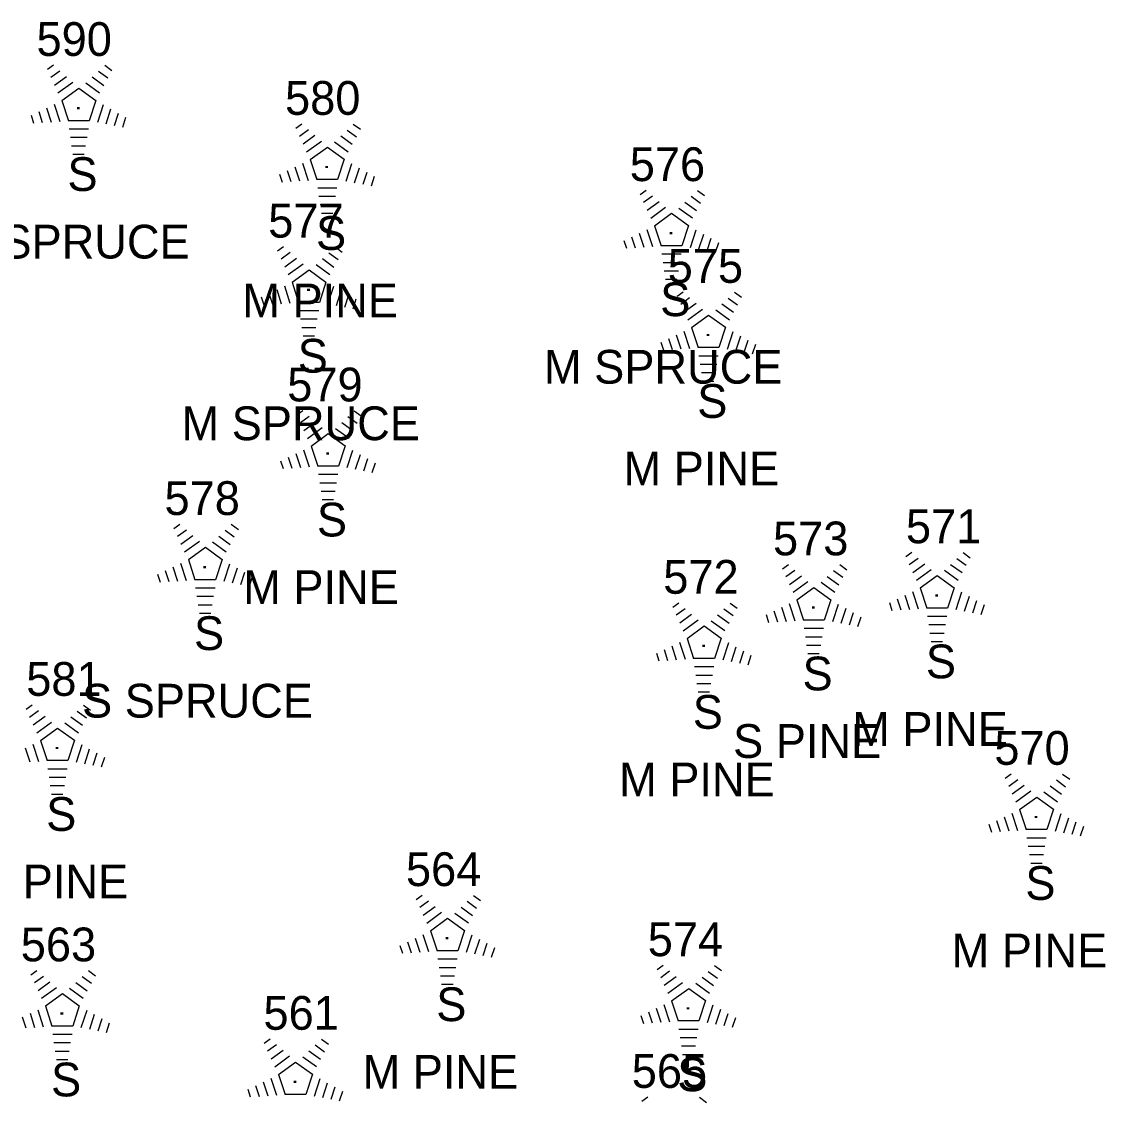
# Model space of a CAD drawing. Extents: x 1545627 to 1546562, y 571176 to 576667.
# Drawn here: x 1546217.9 to 1546282, y 571977 to 572041 of the extents above; entities that cross this region are included whole.
import ezdxf

# ---------------------------------------------------------------- set-up
doc = ezdxf.new("R2010")
doc.units = 0
for name, color, linetype in [('L_A', 7, 'Continuous'), ('L_C', 7, 'Continuous'), ('L_I', 7, 'Continuous'), ('LTC', 7, 'Continuous')]:
    doc.layers.add(name, color=color, linetype=linetype)

msp = doc.modelspace()

# ---------------------------------------------------------------- linework, layer by layer
at = {"layer": 'LTC'}
for p, q in [((1546219.373, 572038.219), (1546219.728, 572038.477)), ((1546222.772, 572038.46), (1546223.191, 572038.155)), ((1546219.583, 572037.754), (1546220.112, 572038.138)), ((1546219.793, 572037.288), (1546220.496, 572037.799)), ((1546222.03, 572037.763), (1546222.709, 572037.269)), ((1546222.4, 572038.111), (1546222.95, 572037.712)), ((1546220.002, 572036.822), (1546220.88, 572037.46)), ((1546221.658, 572037.415), (1546222.468, 572036.826)), ((1546220.227, 572036.367), (1546221.238, 572037.102)), ((1546221.238, 572037.102), (1546222.235, 572036.377)), ((1546219.317, 572035.932), (1546219.588, 572035.096)), ((1546219.772, 572036.148), (1546220.103, 572035.129)), ((1546220.227, 572036.367), (1546220.614, 572035.174)), ((1546222.235, 572036.377), (1546221.844, 572035.174)), ((1546222.673, 572036.106), (1546222.335, 572035.066)), ((1546223.118, 572035.855), (1546222.83, 572034.971)), ((1546218.406, 572035.498), (1546218.558, 572035.03)), ((1546218.861, 572035.715), (1546219.073, 572035.063)), ((1546223.562, 572035.605), (1546223.325, 572034.876)), ((1546224.006, 572035.355), (1546223.82, 572034.781)), ((1546221.844, 572035.174), (1546220.614, 572035.174)), ((1546221.806, 572034.674), (1546220.661, 572034.674)), ((1546234.089, 572034.729), (1546234.443, 572034.986)), ((1546234.299, 572034.264), (1546234.828, 572034.648)), ((1546237.116, 572034.621), (1546237.666, 572034.222)), ((1546237.487, 572034.969), (1546237.906, 572034.665)), ((1546221.722, 572034.174), (1546220.734, 572034.174)), ((1546234.508, 572033.798), (1546235.212, 572034.309)), ((1546234.718, 572033.332), (1546235.596, 572033.97)), ((1546236.374, 572033.924), (1546237.183, 572033.336)), ((1546236.745, 572034.273), (1546237.424, 572033.779)), ((1546221.638, 572033.674), (1546220.807, 572033.674)), ((1546234.942, 572032.877), (1546235.954, 572033.611)), ((1546235.954, 572033.611), (1546236.951, 572032.886)), ((1546221.555, 572033.174), (1546220.88, 572033.174)), ((1546234.488, 572032.658), (1546234.818, 572031.639)), ((1546234.942, 572032.877), (1546235.329, 572031.684)), ((1546236.951, 572032.886), (1546236.56, 572031.684)), ((1546237.388, 572032.616), (1546237.051, 572031.576)), ((1546233.121, 572032.008), (1546233.274, 572031.54)), ((1546233.577, 572032.225), (1546233.789, 572031.573)), ((1546234.032, 572032.442), (1546234.304, 572031.606)), ((1546237.833, 572032.365), (1546237.546, 572031.481)), ((1546238.278, 572032.115), (1546238.041, 572031.386)), ((1546236.56, 572031.684), (1546235.329, 572031.684)), ((1546238.722, 572031.865), (1546238.535, 572031.291)), ((1546236.521, 572031.184), (1546235.377, 572031.184)), ((1546254.468, 572030.805), (1546254.822, 572031.063)), ((1546254.677, 572030.34), (1546255.206, 572030.724)), ((1546257.495, 572030.697), (1546258.044, 572030.298)), ((1546257.866, 572031.045), (1546258.285, 572030.741)), ((1546236.438, 572030.684), (1546235.449, 572030.684)), ((1546236.354, 572030.184), (1546235.522, 572030.184)), ((1546254.887, 572029.874), (1546255.59, 572030.385)), ((1546255.096, 572029.408), (1546255.975, 572030.046)), ((1546257.124, 572030.349), (1546257.803, 572029.855)), ((1546236.27, 572029.684), (1546235.595, 572029.684)), ((1546255.321, 572028.953), (1546256.333, 572029.688)), ((1546256.333, 572029.688), (1546257.33, 572028.963)), ((1546256.753, 572030), (1546257.562, 572029.412)), ((1546255.321, 572028.953), (1546255.708, 572027.76)), ((1546257.33, 572028.963), (1546256.938, 572027.76)), ((1546253.955, 572028.301), (1546254.167, 572027.649)), ((1546254.411, 572028.518), (1546254.682, 572027.682)), ((1546254.866, 572028.734), (1546255.197, 572027.715)), ((1546257.767, 572028.692), (1546257.429, 572027.652)), ((1546258.212, 572028.441), (1546257.924, 572027.557)), ((1546258.656, 572028.191), (1546258.419, 572027.462)), ((1546233.007, 572027.458), (1546233.361, 572027.716)), ((1546236.405, 572027.699), (1546236.824, 572027.394)), ((1546253.5, 572028.084), (1546253.652, 572027.616)), ((1546256.938, 572027.76), (1546255.708, 572027.76)), ((1546259.1, 572027.941), (1546258.914, 572027.367)), ((1546233.216, 572026.993), (1546233.745, 572027.377)), ((1546233.426, 572026.527), (1546234.129, 572027.038)), ((1546235.663, 572027.002), (1546236.342, 572026.508)), ((1546236.034, 572027.351), (1546236.583, 572026.951)), ((1546256.9, 572027.26), (1546255.755, 572027.26)), ((1546233.635, 572026.061), (1546234.514, 572026.699)), ((1546233.86, 572025.606), (1546234.872, 572026.341)), ((1546234.872, 572026.341), (1546235.869, 572025.616)), ((1546235.292, 572026.654), (1546236.101, 572026.065)), ((1546256.816, 572026.76), (1546255.828, 572026.76)), ((1546256.733, 572026.26), (1546255.901, 572026.26)), ((1546233.86, 572025.606), (1546234.247, 572024.413)), ((1546235.869, 572025.616), (1546235.477, 572024.413)), ((1546256.649, 572025.76), (1546255.974, 572025.76)), ((1546232.494, 572024.954), (1546232.706, 572024.303)), ((1546232.95, 572025.171), (1546233.221, 572024.336)), ((1546233.405, 572025.387), (1546233.736, 572024.368)), ((1546236.306, 572025.345), (1546235.968, 572024.306)), ((1546236.751, 572025.095), (1546236.463, 572024.21)), ((1546256.66, 572024.778), (1546257.014, 572025.036)), ((1546260.058, 572025.018), (1546260.477, 572024.714)), ((1546232.039, 572024.738), (1546232.191, 572024.27)), ((1546235.477, 572024.413), (1546234.247, 572024.413)), ((1546237.195, 572024.845), (1546236.958, 572024.115)), ((1546237.639, 572024.594), (1546237.453, 572024.02)), ((1546256.869, 572024.313), (1546257.398, 572024.697)), ((1546257.079, 572023.847), (1546257.782, 572024.358)), ((1546259.316, 572024.322), (1546259.995, 572023.828)), ((1546259.687, 572024.67), (1546260.236, 572024.271)), ((1546235.439, 572023.913), (1546234.294, 572023.913)), ((1546257.288, 572023.381), (1546258.167, 572024.019)), ((1546257.513, 572022.926), (1546258.525, 572023.661)), ((1546258.525, 572023.661), (1546259.522, 572022.936)), ((1546258.945, 572023.973), (1546259.754, 572023.385)), ((1546235.355, 572023.413), (1546234.367, 572023.413)), ((1546235.272, 572022.913), (1546234.44, 572022.913)), ((1546235.188, 572022.413), (1546234.513, 572022.413)), ((1546256.603, 572022.491), (1546256.874, 572021.655)), ((1546257.058, 572022.707), (1546257.389, 572021.688)), ((1546257.513, 572022.926), (1546257.9, 572021.733)), ((1546259.522, 572022.936), (1546259.13, 572021.733)), ((1546259.959, 572022.665), (1546259.621, 572021.625)), ((1546260.404, 572022.414), (1546260.116, 572021.53)), ((1546255.692, 572022.057), (1546255.844, 572021.589)), ((1546256.147, 572022.274), (1546256.359, 572021.622)), ((1546259.13, 572021.733), (1546257.9, 572021.733)), ((1546260.848, 572022.164), (1546260.611, 572021.435)), ((1546261.292, 572021.914), (1546261.106, 572021.34)), ((1546259.092, 572021.233), (1546257.947, 572021.233)), ((1546259.008, 572020.733), (1546258.02, 572020.733)), ((1546258.925, 572020.233), (1546258.093, 572020.233)), ((1546258.841, 572019.733), (1546258.166, 572019.733)), ((1546234.142, 572017.755), (1546234.496, 572018.013)), ((1546237.54, 572017.995), (1546237.959, 572017.691)), ((1546234.351, 572017.29), (1546234.88, 572017.674)), ((1546234.561, 572016.824), (1546235.264, 572017.335)), ((1546236.798, 572017.299), (1546237.477, 572016.805)), ((1546237.169, 572017.647), (1546237.718, 572017.248)), ((1546234.77, 572016.358), (1546235.649, 572016.996)), ((1546234.995, 572015.903), (1546236.007, 572016.638)), ((1546236.007, 572016.638), (1546237.004, 572015.913)), ((1546236.427, 572016.95), (1546237.236, 572016.362)), ((1546234.085, 572015.468), (1546234.356, 572014.632)), ((1546234.54, 572015.684), (1546234.871, 572014.665)), ((1546234.995, 572015.903), (1546235.382, 572014.71)), ((1546237.004, 572015.913), (1546236.612, 572014.71)), ((1546237.441, 572015.642), (1546237.103, 572014.602)), ((1546237.886, 572015.391), (1546237.598, 572014.507)), ((1546233.174, 572015.034), (1546233.326, 572014.566)), ((1546233.629, 572015.251), (1546233.841, 572014.599)), ((1546236.612, 572014.71), (1546235.382, 572014.71)), ((1546238.33, 572015.141), (1546238.093, 572014.412)), ((1546238.774, 572014.891), (1546238.588, 572014.317)), ((1546236.574, 572014.21), (1546235.429, 572014.21)), ((1546236.49, 572013.71), (1546235.502, 572013.71)), ((1546236.407, 572013.21), (1546235.575, 572013.21)), ((1546236.323, 572012.71), (1546235.648, 572012.71)), ((1546226.865, 572011.027), (1546227.22, 572011.284)), ((1546227.075, 572010.561), (1546227.604, 572010.945)), ((1546229.892, 572010.919), (1546230.442, 572010.52)), ((1546230.264, 572011.267), (1546230.683, 572010.962)), ((1546227.284, 572010.095), (1546227.988, 572010.607)), ((1546227.494, 572009.63), (1546228.372, 572010.267)), ((1546229.15, 572010.222), (1546229.96, 572009.633)), ((1546229.522, 572010.57), (1546230.201, 572010.077)), ((1546227.719, 572009.175), (1546228.73, 572009.909)), ((1546228.73, 572009.909), (1546229.727, 572009.184)), ((1546270.196, 572009.352), (1546270.551, 572009.609)), ((1546273.595, 572009.592), (1546274.014, 572009.288)), ((1546227.264, 572008.955), (1546227.595, 572007.936)), ((1546227.719, 572009.175), (1546228.106, 572007.981)), ((1546229.727, 572009.184), (1546229.336, 572007.981)), ((1546230.165, 572008.913), (1546229.827, 572007.874)), ((1546262.895, 572008.637), (1546263.249, 572008.894)), ((1546266.293, 572008.877), (1546266.712, 572008.573)), ((1546270.406, 572008.886), (1546270.935, 572009.27)), ((1546270.616, 572008.42), (1546271.319, 572008.932)), ((1546272.853, 572008.895), (1546273.532, 572008.402)), ((1546273.224, 572009.244), (1546273.773, 572008.845)), ((1546225.898, 572008.306), (1546226.05, 572007.838)), ((1546226.353, 572008.522), (1546226.565, 572007.871)), ((1546226.809, 572008.739), (1546227.08, 572007.904)), ((1546230.609, 572008.663), (1546230.322, 572007.778)), ((1546231.054, 572008.413), (1546230.817, 572007.683)), ((1546263.104, 572008.171), (1546263.633, 572008.556)), ((1546265.922, 572008.529), (1546266.471, 572008.13)), ((1546270.825, 572007.955), (1546271.704, 572008.593)), ((1546271.05, 572007.5), (1546272.061, 572008.234)), ((1546272.061, 572008.234), (1546273.059, 572007.509)), ((1546272.481, 572008.547), (1546273.291, 572007.958)), ((1546229.336, 572007.981), (1546228.106, 572007.981)), ((1546231.498, 572008.162), (1546231.312, 572007.588)), ((1546263.314, 572007.706), (1546264.018, 572008.217)), ((1546263.523, 572007.24), (1546264.402, 572007.878)), ((1546265.18, 572007.832), (1546265.989, 572007.243)), ((1546265.551, 572008.181), (1546266.23, 572007.687)), ((1546229.298, 572007.481), (1546228.153, 572007.481)), ((1546229.214, 572006.981), (1546228.226, 572006.981)), ((1546263.748, 572006.785), (1546264.76, 572007.519)), ((1546264.76, 572007.519), (1546265.757, 572006.794)), ((1546270.14, 572007.064), (1546270.411, 572006.229)), ((1546270.595, 572007.28), (1546270.926, 572006.261)), ((1546271.05, 572007.5), (1546271.437, 572006.306)), ((1546273.059, 572007.509), (1546272.667, 572006.306)), ((1546273.496, 572007.238), (1546273.158, 572006.199)), ((1546273.941, 572006.988), (1546273.653, 572006.103)), ((1546229.13, 572006.481), (1546228.299, 572006.481)), ((1546256.396, 572006.362), (1546256.751, 572006.62)), ((1546259.795, 572006.603), (1546260.214, 572006.298)), ((1546262.838, 572006.349), (1546263.109, 572005.514)), ((1546263.293, 572006.566), (1546263.624, 572005.546)), ((1546263.748, 572006.785), (1546264.135, 572005.591)), ((1546265.757, 572006.794), (1546265.365, 572005.591)), ((1546266.194, 572006.523), (1546265.856, 572005.484)), ((1546269.229, 572006.631), (1546269.381, 572006.163)), ((1546269.684, 572006.848), (1546269.896, 572006.196)), ((1546272.667, 572006.306), (1546271.437, 572006.306)), ((1546274.385, 572006.738), (1546274.148, 572006.008)), ((1546274.829, 572006.488), (1546274.643, 572005.913)), ((1546229.047, 572005.981), (1546228.372, 572005.981)), ((1546256.606, 572005.897), (1546257.135, 572006.281)), ((1546256.816, 572005.431), (1546257.519, 572005.942)), ((1546259.053, 572005.906), (1546259.732, 572005.412)), ((1546259.423, 572006.254), (1546259.973, 572005.855)), ((1546261.927, 572005.916), (1546262.079, 572005.448)), ((1546262.383, 572006.133), (1546262.594, 572005.481)), ((1546266.639, 572006.273), (1546266.351, 572005.388)), ((1546267.083, 572006.023), (1546266.846, 572005.293)), ((1546267.528, 572005.773), (1546267.341, 572005.198)), ((1546272.629, 572005.806), (1546271.484, 572005.806)), ((1546257.025, 572004.965), (1546257.903, 572005.603)), ((1546257.25, 572004.51), (1546258.261, 572005.245)), ((1546258.261, 572005.245), (1546259.258, 572004.52)), ((1546258.681, 572005.558), (1546259.491, 572004.969)), ((1546265.365, 572005.591), (1546264.135, 572005.591)), ((1546265.327, 572005.091), (1546264.183, 572005.091)), ((1546272.545, 572005.306), (1546271.557, 572005.306)), ((1546257.25, 572004.51), (1546257.637, 572003.317)), ((1546259.258, 572004.52), (1546258.867, 572003.317)), ((1546265.243, 572004.591), (1546264.255, 572004.591)), ((1546272.461, 572004.806), (1546271.63, 572004.806)), ((1546255.884, 572003.858), (1546256.096, 572003.206)), ((1546256.34, 572004.075), (1546256.611, 572003.239)), ((1546256.795, 572004.291), (1546257.126, 572003.272)), ((1546259.696, 572004.249), (1546259.358, 572003.209)), ((1546260.14, 572003.998), (1546259.853, 572003.114)), ((1546260.585, 572003.748), (1546260.348, 572003.019)), ((1546265.16, 572004.091), (1546264.328, 572004.091)), ((1546272.378, 572004.306), (1546271.703, 572004.306)), ((1546255.429, 572003.641), (1546255.581, 572003.173)), ((1546258.867, 572003.317), (1546257.637, 572003.317)), ((1546261.029, 572003.498), (1546260.843, 572002.924)), ((1546265.076, 572003.591), (1546264.401, 572003.591)), ((1546258.829, 572002.817), (1546257.684, 572002.817)), ((1546258.745, 572002.317), (1546257.757, 572002.317)), ((1546258.661, 572001.817), (1546257.83, 572001.817)), ((1546258.578, 572001.317), (1546257.903, 572001.317)), ((1546218.113, 572000.314), (1546218.468, 572000.572)), ((1546221.512, 572000.555), (1546221.931, 572000.25)), ((1546218.323, 571999.849), (1546218.852, 572000.233)), ((1546218.532, 571999.383), (1546219.236, 571999.894)), ((1546221.14, 572000.207), (1546221.69, 571999.807)), ((1546218.742, 571998.917), (1546219.62, 571999.555)), ((1546220.398, 571999.51), (1546221.208, 571998.921)), ((1546220.77, 571999.858), (1546221.449, 571999.364)), ((1546218.967, 571998.462), (1546219.978, 571999.197)), ((1546219.978, 571999.197), (1546220.975, 571998.472)), ((1546218.057, 571998.027), (1546218.328, 571997.192)), ((1546218.512, 571998.243), (1546218.843, 571997.224)), ((1546218.967, 571998.462), (1546219.354, 571997.269)), ((1546220.975, 571998.472), (1546220.584, 571997.269)), ((1546221.413, 571998.201), (1546221.075, 571997.162)), ((1546221.857, 571997.951), (1546221.57, 571997.066)), ((1546222.302, 571997.701), (1546222.065, 571996.971)), ((1546222.746, 571997.45), (1546222.56, 571996.876)), ((1546220.584, 571997.269), (1546219.354, 571997.269)), ((1546220.546, 571996.769), (1546219.401, 571996.769)), ((1546220.462, 571996.269), (1546219.474, 571996.269)), ((1546276.085, 571996.229), (1546276.44, 571996.486)), ((1546276.295, 571995.763), (1546276.824, 571996.147)), ((1546279.113, 571996.121), (1546279.662, 571995.721)), ((1546279.484, 571996.469), (1546279.903, 571996.164)), ((1546220.378, 571995.769), (1546219.547, 571995.769)), ((1546276.505, 571995.297), (1546277.208, 571995.809)), ((1546276.714, 571994.831), (1546277.593, 571995.469)), ((1546278.37, 571995.424), (1546279.18, 571994.835)), ((1546278.742, 571995.772), (1546279.421, 571995.279)), ((1546220.295, 571995.269), (1546219.62, 571995.269)), ((1546276.939, 571994.376), (1546277.95, 571995.111)), ((1546277.95, 571995.111), (1546278.948, 571994.386)), ((1546276.484, 571994.157), (1546276.815, 571993.138)), ((1546276.939, 571994.376), (1546277.326, 571993.183)), ((1546278.948, 571994.386), (1546278.556, 571993.183)), ((1546275.118, 571993.508), (1546275.27, 571993.04)), ((1546275.573, 571993.724), (1546275.785, 571993.073)), ((1546276.029, 571993.941), (1546276.3, 571993.106)), ((1546279.385, 571994.115), (1546279.047, 571993.076)), ((1546279.83, 571993.865), (1546279.542, 571992.98)), ((1546280.274, 571993.615), (1546280.037, 571992.885)), ((1546278.556, 571993.183), (1546277.326, 571993.183)), ((1546280.718, 571993.364), (1546280.532, 571992.79)), ((1546278.518, 571992.683), (1546277.373, 571992.683)), ((1546278.434, 571992.183), (1546277.446, 571992.183)), ((1546278.35, 571991.683), (1546277.519, 571991.683)), ((1546278.267, 571991.183), (1546277.592, 571991.183)), ((1546241.208, 571989.045), (1546241.563, 571989.303)), ((1546244.607, 571989.286), (1546245.026, 571988.981)), ((1546241.418, 571988.58), (1546241.947, 571988.964)), ((1546241.628, 571988.114), (1546242.331, 571988.625)), ((1546243.865, 571988.589), (1546244.544, 571988.095)), ((1546244.236, 571988.938), (1546244.785, 571988.538)), ((1546241.837, 571987.648), (1546242.716, 571988.286)), ((1546242.062, 571987.193), (1546243.073, 571987.928)), ((1546243.073, 571987.928), (1546244.071, 571987.203)), ((1546243.493, 571988.241), (1546244.303, 571987.652)), ((1546242.062, 571987.193), (1546242.449, 571986)), ((1546244.071, 571987.203), (1546243.679, 571986)), ((1546240.696, 571986.541), (1546240.908, 571985.89)), ((1546241.152, 571986.758), (1546241.423, 571985.923)), ((1546241.607, 571986.974), (1546241.938, 571985.955)), ((1546244.508, 571986.932), (1546244.17, 571985.893)), ((1546244.953, 571986.682), (1546244.665, 571985.797)), ((1546245.397, 571986.432), (1546245.16, 571985.702)), ((1546240.241, 571986.325), (1546240.393, 571985.857)), ((1546243.679, 571986), (1546242.449, 571986)), ((1546245.841, 571986.181), (1546245.655, 571985.607)), ((1546243.641, 571985.5), (1546242.496, 571985.5)), ((1546255.478, 571984.893), (1546255.833, 571985.151)), ((1546258.876, 571985.133), (1546259.296, 571984.829)), ((1546218.402, 571984.587), (1546218.756, 571984.845)), ((1546218.611, 571984.122), (1546219.14, 571984.506)), ((1546221.8, 571984.828), (1546222.219, 571984.523)), ((1546243.557, 571985), (1546242.569, 571985)), ((1546243.473, 571984.5), (1546242.642, 571984.5)), ((1546255.688, 571984.428), (1546256.217, 571984.812)), ((1546258.505, 571984.785), (1546259.055, 571984.386)), ((1546218.821, 571983.656), (1546219.525, 571984.167)), ((1546221.058, 571984.131), (1546221.737, 571983.637)), ((1546221.429, 571984.479), (1546221.978, 571984.08)), ((1546243.39, 571984), (1546242.715, 571984)), ((1546255.897, 571983.962), (1546256.601, 571984.473)), ((1546256.107, 571983.496), (1546256.985, 571984.134)), ((1546257.763, 571984.088), (1546258.573, 571983.5)), ((1546258.134, 571984.437), (1546258.814, 571983.943)), ((1546219.03, 571983.19), (1546219.909, 571983.828)), ((1546219.255, 571982.735), (1546220.267, 571983.47)), ((1546220.267, 571983.47), (1546221.264, 571982.745)), ((1546220.687, 571983.783), (1546221.496, 571983.194)), ((1546256.332, 571983.041), (1546257.343, 571983.776)), ((1546257.343, 571983.776), (1546258.34, 571983.051)), ((1546219.255, 571982.735), (1546219.642, 571981.542)), ((1546221.264, 571982.745), (1546220.873, 571981.542)), ((1546255.422, 571982.606), (1546255.693, 571981.77)), ((1546255.877, 571982.822), (1546256.208, 571981.803)), ((1546256.332, 571983.041), (1546256.719, 571981.848)), ((1546258.34, 571983.051), (1546257.949, 571981.848)), ((1546258.778, 571982.78), (1546258.44, 571981.74)), ((1546217.89, 571982.083), (1546218.101, 571981.431)), ((1546218.345, 571982.3), (1546218.616, 571981.464)), ((1546218.8, 571982.516), (1546219.131, 571981.497)), ((1546221.701, 571982.474), (1546221.363, 571981.434)), ((1546222.146, 571982.223), (1546221.858, 571981.339)), ((1546222.59, 571981.973), (1546222.353, 571981.244)), ((1546254.511, 571982.172), (1546254.663, 571981.704)), ((1546254.966, 571982.389), (1546255.178, 571981.737)), ((1546259.222, 571982.529), (1546258.935, 571981.645)), ((1546259.667, 571982.279), (1546259.43, 571981.55)), ((1546260.111, 571982.029), (1546259.924, 571981.455)), ((1546220.873, 571981.542), (1546219.642, 571981.542)), ((1546223.035, 571981.723), (1546222.848, 571981.149)), ((1546257.949, 571981.848), (1546256.719, 571981.848)), ((1546257.911, 571981.348), (1546256.766, 571981.348)), ((1546220.834, 571981.042), (1546219.69, 571981.042)), ((1546232.204, 571980.534), (1546232.559, 571980.791)), ((1546235.602, 571980.774), (1546236.022, 571980.47)), ((1546257.827, 571980.848), (1546256.839, 571980.848)), ((1546220.75, 571980.542), (1546219.762, 571980.542)), ((1546220.667, 571980.042), (1546219.835, 571980.042)), ((1546232.414, 571980.068), (1546232.943, 571980.453)), ((1546232.623, 571979.603), (1546233.327, 571980.114)), ((1546234.86, 571980.078), (1546235.54, 571979.584)), ((1546235.231, 571980.426), (1546235.781, 571980.027)), ((1546257.743, 571980.348), (1546256.912, 571980.348)), ((1546220.583, 571979.542), (1546219.908, 571979.542)), ((1546232.833, 571979.137), (1546233.711, 571979.775)), ((1546233.057, 571978.682), (1546234.069, 571979.416)), ((1546234.069, 571979.416), (1546235.066, 571978.691)), ((1546234.489, 571979.729), (1546235.299, 571979.141)), ((1546257.659, 571979.848), (1546256.984, 571979.848)), ((1546232.147, 571978.246), (1546232.419, 571977.411)), ((1546232.603, 571978.463), (1546232.934, 571977.443)), ((1546233.057, 571978.682), (1546233.445, 571977.488)), ((1546235.066, 571978.691), (1546234.675, 571977.488)), ((1546235.504, 571978.421), (1546235.166, 571977.381)), ((1546235.948, 571978.17), (1546235.661, 571977.286)), ((1546231.237, 571977.813), (1546231.389, 571977.345)), ((1546231.692, 571978.03), (1546231.904, 571977.378)), ((1546234.675, 571977.488), (1546233.445, 571977.488)), ((1546236.393, 571977.92), (1546236.156, 571977.191)), ((1546236.837, 571977.67), (1546236.65, 571977.096)), ((1546254.577, 571977.091), (1546254.931, 571977.348)), ((1546257.975, 571977.331), (1546258.394, 571977.027))]:
    msp.add_line(p, q, dxfattribs=at)

# ---------------------------------------------------------------- texts
at = {"layer": 'L_A'}
for p in [(1546220.564, 572031.011), (1546235.28, 572027.521), (1546255.658, 572023.597), (1546234.197, 572020.25), (1546257.85, 572017.57), (1546235.332, 572010.547), (1546228.056, 572003.818), (1546271.387, 572002.144), (1546264.085, 572001.429), (1546257.587, 571999.154), (1546219.304, 571993.106), (1546277.276, 571989.02), (1546242.399, 571981.837), (1546219.592, 571977.379), (1546256.669, 571977.685)]:
    msp.add_text('S', height=2, dxfattribs=at).set_placement(p)
at = {"layer": 'L_C'}
for s, p in [('M SPRUCE', (1546213.682, 572027.011)), ('M PINE', (1546230.917, 572023.521)), ('M SPRUCE', (1546248.776, 572019.597)), ('M SPRUCE', (1546227.315, 572016.25)), ('M PINE', (1546253.488, 572013.57)), ('M PINE', (1546230.97, 572006.547)), ('S SPRUCE', (1546221.426, 571999.818)), ('M PINE', (1546267.025, 571998.144)), ('S PINE', (1546259.975, 571997.429)), ('M PINE', (1546253.225, 571995.154)), ('M PINE', (1546214.942, 571989.106)), ('M PINE', (1546272.914, 571985.02)), ('M PINE', (1546238.037, 571977.837))]:
    msp.add_text(s, height=2, dxfattribs=at).set_placement(p)
at = {"layer": 'L_I'}
for s, p in [('590', (1546218.729, 572039.011)), ('580', (1546233.445, 572035.521)), ('576', (1546253.855, 572031.597)), ('577', (1546232.449, 572028.25)), ('575', (1546256.102, 572025.57)), ('579', (1546233.576, 572018.547)), ('578', (1546226.308, 572011.818)), ('571', (1546270.206, 572010.144)), ('573', (1546262.337, 572009.429)), ('572', (1546255.839, 572007.154)), ('581', (1546218.123, 572001.106)), ('570', (1546275.441, 571997.02)), ('564', (1546240.604, 571989.837)), ('563', (1546217.797, 571985.379)), ('574', (1546254.921, 571985.685)), ('561', (1546232.166, 571981.326)), ('565', (1546253.972, 571977.883))]:
    msp.add_text(s, height=2, dxfattribs=at).set_placement(p)
at = {"layer": 'LTC'}
for p in [(1546221.121, 572036.115), (1546235.836, 572032.625), (1546256.215, 572028.701), (1546234.754, 572025.354), (1546258.407, 572022.674), (1546235.889, 572015.651), (1546228.613, 572008.922), (1546271.944, 572007.248), (1546264.642, 572006.533), (1546258.144, 572004.258), (1546219.861, 571998.21), (1546277.833, 571994.124), (1546242.956, 571986.941), (1546257.226, 571982.789), (1546220.149, 571982.483), (1546233.952, 571978.43)]:
    msp.add_text('.', height=1.037, rotation=270, dxfattribs=at).set_placement(p)

doc.saveas('drawing.dxf')
